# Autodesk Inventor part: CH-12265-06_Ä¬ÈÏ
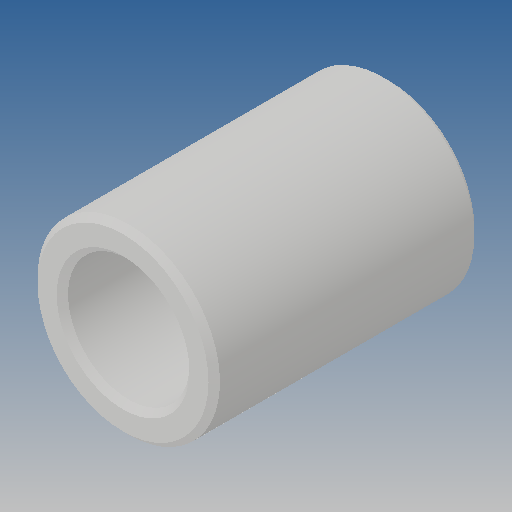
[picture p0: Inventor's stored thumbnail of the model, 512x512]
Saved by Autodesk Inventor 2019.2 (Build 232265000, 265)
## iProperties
Created: 2012-09
Part Number: CH-12265-06_Ä¬ÈÏ
Material: Ogólny
Document SubType Name: Modeling
Designer: CADENGINEERING4
Density: 1 g/cm^3
Appearance: Domyślna
Author: CADENGINEERING4
Revision Number: ÈÎºÎ
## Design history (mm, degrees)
feature "NONE"
node "Bryła1"
